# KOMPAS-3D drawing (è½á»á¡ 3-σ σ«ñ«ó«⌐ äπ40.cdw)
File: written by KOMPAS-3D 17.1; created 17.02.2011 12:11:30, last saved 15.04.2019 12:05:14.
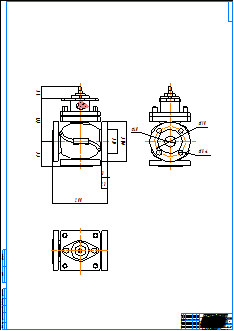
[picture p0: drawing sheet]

Title block, sheet 1: name: Клапан 3-х ходовой Ду40; material: Внимание! Данный продукт является объектом авторского права ООО «Торговый Дом АДЛ». / Запрещается изменение, копирование, распространение / (в том числе путем копирования на другие сайты и ресурсы в Интернете) / или любое иное использование информации и объектов без предварительного / согласия правообладателя (ООО «Торговый Дом АДЛ»).; scale: 1:1; sheets: 1; organisation: ООО "Торговый дом АДЛ"; sheet format: A0; stored path: \\adlc.lan\data\АДЛ_ПКД\3D-модели\ADL production\Клапаны ГРАНРЕГ\Трёхходовой клапан КМ307Ф\KOMPAS 2D\Клапан 3-х ходовой Ду40.cdw

Views: Спереди 1, Проекционный вид 2, Проекционный вид 3
Dimensions and other numbers on the sheet: 90; 156; 43; 200; 3; 23; 110; 18; 40; 88; 145; 1:1; 1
